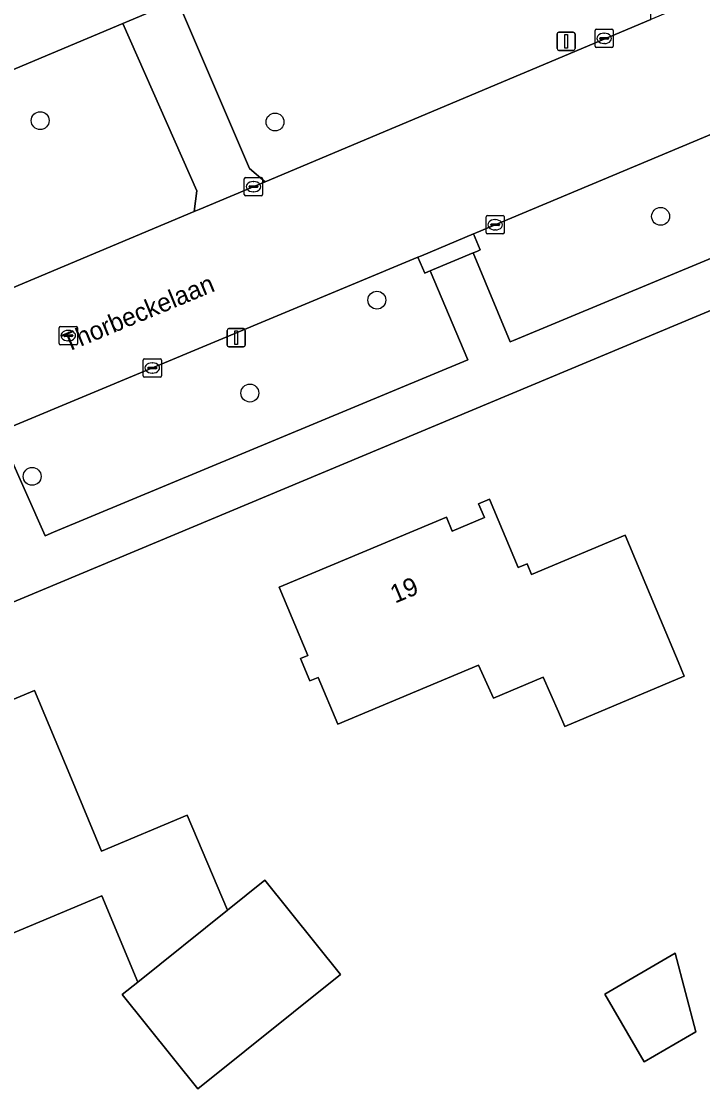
# Model space of a CAD drawing. Extents: x 162417 to 163722, y 384268 to 385417.
# Drawn here: x 163446.4 to 163483.6, y 384869.2 to 384927.8 of the extents above; entities that cross this region are included whole.
import ezdxf

# ---------------------------------------------------------------- set-up
doc = ezdxf.new("R2010")
doc.units = 0
for name, color, linetype in [('IMGEO_Berm_groen', 7, 'Continuous'), ('IMGEO_Boom', 7, 'Continuous'), ('IMGEO_Erf', 7, 'Continuous'), ('IMGEO_Groenvoorziening', 7, 'Continuous'), ('IMGEO_Kolk', 7, 'Continuous'), ('IMGEO_Lichtmast', 7, 'Continuous'), ('IMGEO_Openbare_ruimte_label', 7, 'Continuous'), ('IMGEO_Pand', 7, 'Continuous'), ('IMGEO_Pand_nummerreeks', 7, 'Continuous'), ('IMGEO_Rijbaan_lokaal_gesloten', 7, 'Continuous'), ('IMGEO_Rioolput', 7, 'Continuous'), ('IMGEO_Voetpad_open', 7, 'Continuous')]:
    doc.layers.add(name, color=color, linetype=linetype)

msp = doc.modelspace()

# ---------------------------------------------------------------- linework, layer by layer
at = {"layer": 'IMGEO_Berm_groen'}
msp.add_lwpolyline([(163491.093, 384924.544), (163471.257, 384916.239), (163471.068, 384916.16), (163471.435, 384915.284), (163471.255, 384915.199), (163471.064, 384915.12), (163473.081, 384910.255), (163473.27, 384910.334), (163497.491, 384920.419)], dxfattribs=at)
msp.add_lwpolyline([(163468.711, 384914.14), (163468.618, 384914.099), (163468.411, 384914.007), (163468.041, 384914.893), (163446.057, 384905.716), (163445.138, 384905.339), (163445.58, 384904.341), (163447.653, 384899.653), (163448.119, 384899.859), (163470.764, 384909.278)], close=True, dxfattribs=at)
at = {"layer": 'IMGEO_Boom'}
for centre in [(163447.383, 384922.353), (163460.224, 384922.279), (163481.307, 384917.119), (163465.793, 384912.54), (163458.85, 384907.459), (163446.943, 384902.906)]:
    msp.add_circle(centre, 0.489, dxfattribs=at)
at = {"layer": 'IMGEO_Erf'}
for points in [[(163366.55, 384967.171), (163368.242, 384964.531), (163368.391, 384964.299), (163379.349, 384947.426), (163379.982, 384947.768), (163380.971, 384945.978), (163382.418, 384943.603), (163394.29, 384925.305), (163394.506, 384924.972), (163396.543, 384921.829), (163396.623, 384921.705), (163400.169, 384916.215), (163405.67, 384907.984), (163444.074, 384924.391), (163451.907, 384927.667), (163452.25, 384927.811), (163454.895, 384928.917), (163476.005, 384937.8), (163477.129, 384938.273), (163479.466, 384939.261), (163494.207, 384945.241)], [(163565.372, 384794.06), (163550.928, 384821.281), (163500, 384915.752), (163498.731, 384918.106), (163416.764, 384883.847), (163435.391, 384860.693), (163437.735, 384857.778), (163449.614, 384843.069), (163449.843, 384842.786), (163451.746, 384840.437), (163452.011, 384840.109), (163461.716, 384828.124), (163463.926, 384825.396), (163473.971, 384812.925)]]:
    msp.add_lwpolyline(points, dxfattribs=at)
for points in [[(163475.723, 384890.03), (163474.893, 384891.931), (163472.17, 384890.783), (163471.343, 384892.574), (163463.652, 384889.356), (163462.581, 384891.916), (163462.132, 384891.728), (163461.623, 384892.944), (163462.012, 384893.106), (163460.445, 384896.85), (163469.595, 384900.678), (163469.916, 384899.913), (163471.669, 384900.647), (163471.348, 384901.412), (163471.956, 384901.666), (163473.524, 384897.917), (163474.011, 384898.121), (163474.251, 384897.547), (163479.374, 384899.691), (163481.304, 384895.079), (163482.263, 384892.785), (163482.599, 384891.982), (163476.071, 384889.233)], [(163442.825, 384876.648), (163439.997, 384883.414), (163436.056, 384881.766), (163434.339, 384885.871), (163447.071, 384891.193), (163448.999, 384886.58), (163450.737, 384882.421), (163455.413, 384884.376), (163457.624, 384879.188), (163459.673, 384880.829), (163463.8, 384875.678), (163455.995, 384869.426), (163451.868, 384874.577), (163452.721, 384875.26), (163450.755, 384879.963)], [(163480.416, 384870.902), (163478.262, 384874.595), (163482.106, 384876.838), (163483.229, 384872.543)]]:
    msp.add_lwpolyline(points, close=True, dxfattribs=at)
at = {"layer": 'IMGEO_Groenvoorziening'}
msp.add_lwpolyline([(163480.777, 384927.888), (163480.791, 384929.164), (163478.195, 384934.989), (163476.005, 384937.8), (163454.895, 384928.917), (163458.823, 384919.731), (163459.676, 384919.014)], close=True, dxfattribs=at)
for points in [[(163451.907, 384927.667), (163444.074, 384924.391), (163405.67, 384907.984), (163400.169, 384916.215), (163396.623, 384921.705), (163396.543, 384921.829), (163392.848, 384920.991), (163386.542, 384916.841), (163386.043, 384915.852), (163386.251, 384915.578), (163400.236, 384898.404)], [(163407.071, 384896.895), (163455.799, 384917.384), (163455.951, 384918.519), (163451.907, 384927.667)]]:
    msp.add_lwpolyline(points, dxfattribs=at)
at = {"layer": 'IMGEO_Kolk'}
for p, q in [((163477.721, 384926.424), (163477.721, 384927.276)), ((163477.796, 384927.35), (163478.648, 384927.35)), ((163478.722, 384927.276), (163478.722, 384926.424)), ((163477.98, 384926.844), (163477.98, 384926.856)), ((163478.418, 384926.807), (163478.02, 384926.807)), ((163478.023, 384926.893), (163478.421, 384926.893)), ((163478.209, 384927.13), (163478.234, 384927.13)), ((163478.464, 384926.856), (163478.464, 384926.844)), ((163478.648, 384926.35), (163477.796, 384926.35)), ((163478.232, 384926.57), (163478.207, 384926.57)), ((163458.544, 384918.317), (163458.544, 384919.169)), ((163458.619, 384919.243), (163459.471, 384919.243)), ((163459.032, 384919.023), (163459.057, 384919.023)), ((163459.545, 384919.169), (163459.545, 384918.317)), ((163458.803, 384918.737), (163458.803, 384918.749)), ((163459.241, 384918.7), (163458.843, 384918.7)), ((163458.846, 384918.786), (163459.244, 384918.786)), ((163459.055, 384918.463), (163459.03, 384918.463)), ((163459.287, 384918.749), (163459.287, 384918.737)), ((163459.471, 384918.243), (163458.619, 384918.243)), ((163471.761, 384916.234), (163471.761, 384917.086)), ((163471.836, 384917.16), (163472.688, 384917.16)), ((163472.063, 384916.703), (163472.461, 384916.703)), ((163472.249, 384916.94), (163472.274, 384916.94)), ((163472.762, 384917.086), (163472.762, 384916.234)), ((163472.688, 384916.16), (163471.836, 384916.16)), ((163472.02, 384916.654), (163472.02, 384916.666)), ((163472.458, 384916.617), (163472.06, 384916.617)), ((163472.272, 384916.38), (163472.247, 384916.38)), ((163472.504, 384916.666), (163472.504, 384916.654)), ((163453.012, 384908.405), (163453.012, 384909.257)), ((163453.087, 384909.331), (163453.939, 384909.331)), ((163453.5, 384909.111), (163453.525, 384909.111)), ((163454.013, 384909.257), (163454.013, 384908.405)), ((163453.271, 384908.825), (163453.271, 384908.837)), ((163453.709, 384908.788), (163453.311, 384908.788)), ((163453.314, 384908.874), (163453.712, 384908.874)), ((163453.523, 384908.551), (163453.498, 384908.551)), ((163453.755, 384908.837), (163453.755, 384908.825)), ((163453.939, 384908.331), (163453.087, 384908.331))]:
    msp.add_line(p, q, dxfattribs=at)
for points in [[(163477.721, 384926.424), (163477.721, 384927.276)], [(163477.796, 384927.35), (163478.648, 384927.35)], [(163478.722, 384927.276), (163478.722, 384926.424)], [(163478.648, 384926.35), (163477.796, 384926.35)], [(163458.544, 384918.317), (163458.544, 384919.169)], [(163458.619, 384919.243), (163459.471, 384919.243)], [(163459.545, 384919.169), (163459.545, 384918.317)], [(163459.471, 384918.243), (163458.619, 384918.243)], [(163471.761, 384916.234), (163471.761, 384917.086)], [(163471.836, 384917.16), (163472.688, 384917.16)], [(163472.762, 384917.086), (163472.762, 384916.234)], [(163472.688, 384916.16), (163471.836, 384916.16)], [(163453.012, 384908.405), (163453.012, 384909.257)], [(163453.087, 384909.331), (163453.939, 384909.331)], [(163454.013, 384909.257), (163454.013, 384908.405)], [(163453.939, 384908.331), (163453.087, 384908.331)]]:
    msp.add_lwpolyline(points, dxfattribs=at)
for centre, radius, start, end in [((163477.798, 384927.274), 0.0765, 91.55205, 178.44795), ((163477.798, 384927.274), 0.0765, 91.55205, 178.44795), ((163478.646, 384927.274), 0.0765, 1.55205, 88.44795), ((163478.646, 384927.274), 0.0765, 1.55205, 88.44795), ((163478.02, 384926.853), 0.0403, 85.87752, 175.75265), ((163478.017, 384926.843), 0.0366, 178.93798, 274.71019), ((163478.421, 384926.85), 0.043, 264.86636, 352.45326), ((163478.425, 384926.855), 0.0386, 1.73085, 96.63898), ((163477.798, 384926.426), 0.0765, 181.55205, 268.44795), ((163477.798, 384926.426), 0.0765, 181.55205, 268.44795), ((163478.646, 384926.426), 0.0765, 271.55205, 358.44795), ((163478.646, 384926.426), 0.0765, 271.55205, 358.44795), ((163458.621, 384919.167), 0.0765, 91.55205, 178.44795), ((163458.621, 384919.167), 0.0765, 91.55205, 178.44795), ((163459.469, 384919.167), 0.0765, 1.55205, 88.44795), ((163459.469, 384919.167), 0.0765, 1.55205, 88.44795), ((163458.843, 384918.746), 0.0403, 85.87752, 175.75265), ((163458.84, 384918.736), 0.0366, 178.93798, 274.71019), ((163459.244, 384918.743), 0.043, 264.86636, 352.45326), ((163459.248, 384918.748), 0.0386, 1.73085, 96.63898), ((163458.621, 384918.319), 0.0765, 181.55205, 268.44795), ((163458.621, 384918.319), 0.0765, 181.55205, 268.44795), ((163459.469, 384918.319), 0.0765, 271.55205, 358.44795), ((163459.469, 384918.319), 0.0765, 271.55205, 358.44795), ((163471.838, 384917.084), 0.0765, 91.55205, 178.44795), ((163471.838, 384917.084), 0.0765, 91.55205, 178.44795), ((163472.06, 384916.663), 0.0403, 85.87752, 175.75265), ((163472.465, 384916.665), 0.0386, 1.73085, 96.63898), ((163472.686, 384917.084), 0.0765, 1.55205, 88.44795), ((163472.686, 384917.084), 0.0765, 1.55205, 88.44795), ((163471.838, 384916.236), 0.0765, 181.55205, 268.44795), ((163471.838, 384916.236), 0.0765, 181.55205, 268.44795), ((163472.057, 384916.653), 0.0366, 178.93798, 274.71019), ((163472.461, 384916.66), 0.043, 264.86636, 352.45326), ((163472.686, 384916.236), 0.0765, 271.55205, 358.44795), ((163472.686, 384916.236), 0.0765, 271.55205, 358.44795), ((163453.089, 384909.255), 0.0765, 91.55205, 178.44795), ((163453.089, 384909.255), 0.0765, 91.55205, 178.44795), ((163453.937, 384909.255), 0.0765, 1.55205, 88.44795), ((163453.937, 384909.255), 0.0765, 1.55205, 88.44795), ((163453.311, 384908.834), 0.0403, 85.87752, 175.75265), ((163453.308, 384908.824), 0.0366, 178.93798, 274.71019), ((163453.712, 384908.831), 0.043, 264.86636, 352.45326), ((163453.716, 384908.836), 0.0386, 1.73085, 96.63898), ((163453.089, 384908.407), 0.0765, 181.55205, 268.44795), ((163453.089, 384908.407), 0.0765, 181.55205, 268.44795), ((163453.937, 384908.407), 0.0765, 271.55205, 358.44795), ((163453.937, 384908.407), 0.0765, 271.55205, 358.44795)]:
    msp.add_arc(centre, radius, start, end, dxfattribs=at)
for centre, major_axis, ratio, start_param, end_param in [((163478.208, 384926.85), (-0.387, 0.002), 0.722429, 4.712389, 7.853982), ((163478.233, 384926.85), (-0.39, 0.002), 0.717154, 1.570796, 4.712389), ((163459.031, 384918.743), (-0.387, 0.002), 0.722429, 4.712389, 7.853982), ((163459.056, 384918.743), (-0.39, 0.002), 0.717154, 1.570796, 4.712389), ((163472.248, 384916.66), (-0.387, 0.002), 0.722429, 4.712389, 7.853982), ((163472.273, 384916.66), (-0.39, 0.002), 0.717154, 1.570796, 4.712389), ((163453.499, 384908.831), (-0.387, 0.002), 0.722429, 4.712389, 7.853982), ((163453.524, 384908.831), (-0.39, 0.002), 0.717154, 1.570796, 4.712389)]:
    msp.add_ellipse(centre, major_axis=major_axis, ratio=ratio, start_param=start_param, end_param=end_param, dxfattribs=at)
at = {"layer": 'IMGEO_Lichtmast'}
for p, q in [((163475.643, 384926.291), (163475.643, 384927.091)), ((163475.643, 384927.091), (163475.643, 384926.291)), ((163475.743, 384927.191), (163476.533, 384927.191)), ((163476.533, 384927.191), (163475.743, 384927.191)), ((163476.633, 384927.091), (163476.633, 384926.291)), ((163476.633, 384926.291), (163476.633, 384927.091)), ((163476.533, 384926.191), (163475.743, 384926.191)), ((163475.743, 384926.191), (163476.533, 384926.191)), ((163457.605, 384910.086), (163457.605, 384910.886)), ((163457.605, 384910.886), (163457.605, 384910.086)), ((163457.705, 384910.986), (163458.495, 384910.986)), ((163458.495, 384910.986), (163457.705, 384910.986)), ((163458.595, 384910.886), (163458.595, 384910.086)), ((163458.595, 384910.086), (163458.595, 384910.886)), ((163458.495, 384909.986), (163457.705, 384909.986)), ((163457.705, 384909.986), (163458.495, 384909.986))]:
    msp.add_line(p, q, dxfattribs=at)
for points in [[(163476.063, 384927.066), (163476.213, 384927.066), (163476.213, 384926.316), (163476.063, 384926.316), (163476.063, 384927.066)], [(163458.025, 384910.861), (163458.175, 384910.861), (163458.175, 384910.111), (163458.025, 384910.111), (163458.025, 384910.861)]]:
    msp.add_lwpolyline(points, dxfattribs=at)
for centre, start, end in [((163475.743, 384927.091), 90, 180), ((163475.743, 384927.091), 90, 180), ((163476.533, 384927.091), 0, 90), ((163476.533, 384927.091), 360, 90), ((163475.743, 384926.291), 180, 270), ((163475.743, 384926.291), 180, 270), ((163476.533, 384926.291), 270, 0), ((163476.533, 384926.291), 270, 0), ((163457.705, 384910.886), 90, 180), ((163457.705, 384910.886), 90, 180), ((163458.495, 384910.886), 0, 90), ((163458.495, 384910.886), 360, 90), ((163457.705, 384910.086), 180, 270), ((163457.705, 384910.086), 180, 270), ((163458.495, 384910.086), 270, 0), ((163458.495, 384910.086), 270, 0)]:
    msp.add_arc(centre, 0.1, start, end, dxfattribs=at)
at = {"layer": 'IMGEO_Pand'}
for points in [[(163479.374, 384899.691), (163474.251, 384897.547), (163474.011, 384898.121), (163473.524, 384897.917), (163471.956, 384901.666), (163471.348, 384901.412), (163471.669, 384900.647), (163469.916, 384899.913), (163469.595, 384900.678), (163460.445, 384896.85), (163462.012, 384893.106), (163461.623, 384892.944), (163462.132, 384891.728), (163462.581, 384891.916), (163463.652, 384889.356), (163471.343, 384892.574), (163472.17, 384890.783), (163474.893, 384891.931), (163475.723, 384890.03), (163476.071, 384889.233), (163482.599, 384891.982), (163482.263, 384892.785), (163481.304, 384895.079)], [(163452.721, 384875.26), (163457.624, 384879.188), (163455.413, 384884.376), (163450.737, 384882.421), (163448.999, 384886.58), (163447.071, 384891.193), (163434.339, 384885.871), (163436.056, 384881.766), (163439.997, 384883.414), (163442.825, 384876.648), (163450.755, 384879.963)], [(163452.721, 384875.26), (163451.868, 384874.577), (163455.995, 384869.426), (163463.8, 384875.678), (163459.673, 384880.829), (163457.624, 384879.188)], [(163478.262, 384874.595), (163480.416, 384870.902), (163483.229, 384872.543), (163482.106, 384876.838)]]:
    msp.add_lwpolyline(points, close=True, dxfattribs=at)
at = {"layer": 'IMGEO_Rijbaan_lokaal_gesloten'}
for points in [[(163496.246, 384922.739), (163497.491, 384920.419), (163503.817, 384922.872), (163502.633, 384925.084), (163500.82, 384928.465), (163500, 384929.981), (163497.361, 384934.859), (163493.3, 384933.155), (163484.425, 384929.423), (163480.987, 384927.976), (163480.777, 384927.888), (163459.676, 384919.014), (163456.078, 384917.501), (163455.799, 384917.384), (163407.071, 384896.895)], [(163441.787, 384903.962), (163442.907, 384904.422), (163445.138, 384905.339), (163446.057, 384905.716), (163468.041, 384914.893), (163468.225, 384914.97), (163471.068, 384916.16), (163471.257, 384916.239), (163491.093, 384924.544)]]:
    msp.add_lwpolyline(points, dxfattribs=at)
at = {"layer": 'IMGEO_Rioolput'}
for p, q in [((163448.417, 384910.175), (163448.417, 384911.027)), ((163448.492, 384911.101), (163449.344, 384911.101)), ((163448.905, 384910.881), (163448.93, 384910.881)), ((163449.418, 384911.027), (163449.418, 384910.175)), ((163448.676, 384910.595), (163448.676, 384910.607)), ((163449.114, 384910.558), (163448.716, 384910.558)), ((163448.719, 384910.644), (163449.117, 384910.644)), ((163448.928, 384910.321), (163448.903, 384910.321)), ((163449.16, 384910.607), (163449.16, 384910.595)), ((163449.344, 384910.101), (163448.492, 384910.101))]:
    msp.add_line(p, q, dxfattribs=at)
for points in [[(163448.417, 384910.175), (163448.417, 384911.027)], [(163448.492, 384911.101), (163449.344, 384911.101)], [(163449.418, 384911.027), (163449.418, 384910.175)], [(163449.344, 384910.101), (163448.492, 384910.101)]]:
    msp.add_lwpolyline(points, dxfattribs=at)
for centre, radius, start, end in [((163448.494, 384911.025), 0.0765, 91.55205, 178.44795), ((163448.494, 384911.025), 0.0765, 91.55205, 178.44795), ((163449.342, 384911.025), 0.0765, 1.55205, 88.44795), ((163449.342, 384911.025), 0.0765, 1.55205, 88.44795), ((163448.716, 384910.604), 0.0403, 85.87752, 175.75265), ((163448.713, 384910.594), 0.0366, 178.93798, 274.71019), ((163449.117, 384910.601), 0.043, 264.86636, 352.45326), ((163449.121, 384910.606), 0.0386, 1.73085, 96.63898), ((163448.494, 384910.177), 0.0765, 181.55205, 268.44795), ((163448.494, 384910.177), 0.0765, 181.55205, 268.44795), ((163449.342, 384910.177), 0.0765, 271.55205, 358.44795), ((163449.342, 384910.177), 0.0765, 271.55205, 358.44795)]:
    msp.add_arc(centre, radius, start, end, dxfattribs=at)
for centre, major_axis, ratio, start_param, end_param in [((163448.904, 384910.601), (-0.387, 0.002), 0.722429, 4.712389, 7.853982), ((163448.929, 384910.601), (-0.39, 0.002), 0.717154, 1.570796, 4.712389)]:
    msp.add_ellipse(centre, major_axis=major_axis, ratio=ratio, start_param=start_param, end_param=end_param, dxfattribs=at)
at = {"layer": 'IMGEO_Voetpad_open'}
for points in [[(163454.895, 384928.917), (163452.25, 384927.811), (163451.907, 384927.667), (163455.951, 384918.519), (163455.799, 384917.384), (163456.078, 384917.501), (163459.676, 384919.014), (163458.823, 384919.731)], [(163498.731, 384918.106), (163497.491, 384920.419), (163473.27, 384910.334), (163473.081, 384910.255), (163471.064, 384915.12), (163468.838, 384914.197), (163468.711, 384914.14), (163470.764, 384909.278), (163448.119, 384899.859), (163447.653, 384899.653), (163445.58, 384904.341), (163443.745, 384903.492), (163443.384, 384903.314), (163442.277, 384902.833), (163444.255, 384898.281), (163411.476, 384884.508), (163413.249, 384882.384), (163416.764, 384883.847)], [(163471.064, 384915.12), (163471.255, 384915.199), (163471.435, 384915.284), (163471.068, 384916.16), (163468.225, 384914.97), (163468.041, 384914.893), (163468.411, 384914.007), (163468.618, 384914.099), (163468.711, 384914.14), (163468.838, 384914.197)]]:
    msp.add_lwpolyline(points, close=True, dxfattribs=at)

# ---------------------------------------------------------------- texts
at = {"layer": 'IMGEO_Openbare_ruimte_label'}
msp.add_text('Thorbeckelaan', height=1, rotation=22.46118, dxfattribs=at).set_placement((163448.833, 384909.678))
at = {"layer": 'IMGEO_Pand_nummerreeks'}
msp.add_text('19', height=1, rotation=22.70632, dxfattribs=at).set_placement((163466.788, 384895.948))

doc.saveas('drawing.dxf')
